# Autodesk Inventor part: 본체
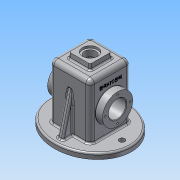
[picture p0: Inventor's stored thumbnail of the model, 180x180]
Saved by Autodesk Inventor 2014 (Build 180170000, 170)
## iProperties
Created: 2017-07
Part Number: 본체
Material: 알루미늄 6061
Document SubType Name: Modeling
Designer: 학생용
Density: 2.71 g/cm^3
Appearance: 알루미늄 - 평지
Mass: 894.559 g
Surface Area: 979.096 cm^2
Volume: 330.096 cm^3
Author: 학생용
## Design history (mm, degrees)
sketch "스케치2"
  geometry: L1 (-75, -65)-(75, -65); L2 (75, -65)-(75, 65); L3 (75, 65)-(-75, 65); L4 (-75, 65)-(-75, -65); L5 (-75, -65)-(75, 65); L6 (75, -65)-(-75, 65); 4 further points; 1 other entity
  constraints: 12 end point, 6 midpoint, 2 horizontal, 2 parallel, 1 perpendicular, 4 other
  dimensions: "d1" = 150 distance of L2.end L3.end; "d2" = 130 distance of L1.end L2.end
extrude "돌출1" new body sketch "스케치2" distance "d3" = 10; taper "d4" = 0 deg
sketch "스케치3"
  geometry: L1 (37, 10)-(-37, 10); L2 (-37, 10)-(-37, 110); L3 (-37, 110)-(37, 110); L4 (37, 110)-(37, 10); L5 (75, 10)-(-75, 10) reference; 2 further points
  constraints: 8 end point, 2 parallel, 1 collinear, 1 horizontal, 1 midpoint, 1 perpendicular, 1 vertical alignment
  dimensions: "d5" = 74 distance of L2.end L3.end; "d6" = 110 distance from line of L3 point (0, 0)
extrude "돌출2" join sketch "스케치3" stored distance "d7" = 74; taper "d8" = 0 deg
fillet "모깎기1" dims "d9" = 8
fillet "모깎기2" dims "d10" = 8
feature "쉘1" dims "d11" = 10, "d12" = 5
sketch "스케치4"
  geometry: L1 (-75, 0)-(-75, 10) reference; L2 (-75, 10)-(-37, 10) reference; L3 (-37, 10)-(-37, 102) reference; L4 (-29, 110)-(29, 110) reference; L5 (37, 102)-(37, 10) reference; L6 (37, 10)-(75, 10) reference; L7 (75, 10)-(75, 0) reference; L8 (75, 0)-(32, 0) reference; L9 (32, 0)-(32, 102) reference; L10 (29, 105)-(-29, 105) reference; L11 (-32, 102)-(-32, 0) reference; L12 (-32, 0)-(-75, 0) reference; L13 (32, 82.5)-(25, 75.5); L14 (25, 75.5)-(25, 55); L15 (25, 55)-(32, 55); L16 (32, 82.5)-(32, 55); L17 (-29, 0)-(29, 0) reference; A1 r 8 centre (-29, 102) between (-29, 110) and (-37, 102) reference; A2 r 8 centre (29, 102) between (37, 102) and (29, 110) reference; A3 r 3 centre (29, 102) between (32, 102) and (29, 105) reference; A4 r 3 centre (-29, 102) between (-29, 105) and (-32, 102) reference; 1 further point
  constraints: 8 end point, 2 perpendicular, 2 point on line, 1 collinear
  dimensions: "d13" = 55 distance between parallel lines of L17 L15; "d14" = 55 diameter of L13.start L15; "d15" = 7 distance between parallel lines of L14 L16; "d16" = 135 deg angle of L9 L13
revolve "회전1" sketch "스케치4" stored, may be unused: angle "d17" = 90 deg
node "작업 평면1"
sketch "스케치5"
  geometry: C1 r 27.5 at (0, 55); 1 further point
  constraints: 1 centre point, 1 vertical alignment
  dimensions: "d19" = 55 distance of point (0, 0) C1.centre; "d20" = 55 diameter of C1
extrude "돌출3" join sketch "스케치5" stored distance "d21" = 74; taper "d22" = 0 deg
node "작업 평면2"
sketch "스케치6"
  geometry: L1 (-20, -20)-(20, -20); L2 (20, -20)-(20, 20); L3 (20, 20)-(-20, 20); L4 (-20, 20)-(-20, -20); L5 (-20, -20)-(20, 20); L6 (20, -20)-(-20, 20); 1 further point
  constraints: 12 end point, 2 midpoint, 2 parallel, 1 horizontal, 1 perpendicular
  dimensions: "d24" = 40 distance of L2.end L3.end; "d25" = 40 distance of L1.end L2.end
extrude "돌출4" join sketch "스케치6" stored distance "d26" = 74; taper "d27" = 0 deg
feature "면 기울기1" dims angle "d28" = 5 deg
sketch "스케치7"
  geometry: 2 further points
  constraints: 1 coincident
hole "구멍1" sketch "스케치7" at (0, 0) diameter "d29" = 21; stored, may be unused: countersink angle "d33" = 90 deg, drill point angle "d35" = 118 deg; dims "d30" = 6, "d31" = 28, "d32" = 4, "d34" = 8
sketch "스케치8"
  geometry: L1 (-65, 0)-(-65, 10) reference; L2 (-65, 10)-(-37, 10) reference; L3 (-37, 10)-(-37, 102) reference; L4 (-29, 110)-(-20, 110) reference; L5 (-20, 110)-(-19.125, 120) reference; L6 (-19.125, 120)-(-14, 120) reference; L7 (-14, 120)-(-14, 116) reference; L8 (-14, 116)-(-10.5, 116) reference; L9 (-10.5, 116)-(-10.5, 105) reference; L10 (-10.5, 105)-(-29, 105) reference; L11 (-32, 102)-(-32, 0) reference; L12 (-32, 0)-(-65, 0) reference; L13 (65, 10)-(65, 0) reference; L14 (65, 0)-(32, 0) reference; L15 (32, 0)-(32, 102) reference; L16 (29, 105)-(10.5, 105) reference; L17 (10.5, 105)-(10.5, 116) reference; L18 (10.5, 116)-(14, 116) reference; L19 (14, 116)-(14, 120) reference; L20 (14, 120)-(19.125, 120) reference; L21 (19.125, 120)-(20, 110) reference; L22 (20, 110)-(29, 110) reference; L23 (37, 102)-(37, 10) reference; L24 (37, 10)-(65, 10) reference; L25 (-55, 10)-(-37, 82.194); A1 r 8 centre (-29, 102) between (-29, 110) and (-37, 102) reference; A2 r 3 centre (-29, 102) between (-29, 105) and (-32, 102) reference; A3 r 3 centre (29, 102) between (32, 102) and (29, 105) reference; A4 r 8 centre (29, 102) between (37, 102) and (29, 110) reference; 1 further point
  constraints: 2 end point, 2 point on line
  dimensions: "d36" = 10 distance from line of L1 L25.start; "d37" = 14 deg angle of L25 L1
feature "리브1" sketch "스케치8" dims "d38" = 1, "d39" = 10, "d40" = 0, "d41" = 0, "d42" = 1, "d43" = 1
hole "구멍2" diameter "d46" = 32; stored, may be unused: countersink angle "d50" = 90 deg, drill point angle "d52" = 118 deg; dims "d44" = 10, "d45" = 10, "d47" = 6, "d48" = 28, "d49" = 4, "d51" = 8
sketch "스케치9"
  geometry: 2 further points
  constraints: 1 horizontal alignment
  dimensions: "d53" = 58 distance of point (58, 0) point (0, 0)
hole "구멍3" sketch "스케치9" at (58, 0) diameter "d54" = 10; stored, may be unused: countersink angle "d58" = 90 deg, drill point angle "d60" = 118 deg; dims "d55" = 6, "d56" = 28, "d57" = 4, "d59" = 8
sketch "스케치10"
  geometry: L1 (-110, 9.875)-(-110, 48.125) reference; L2 (-92, -8)-(0, -8) reference; 2 further points
  constraints: 1 other
  dimensions: "d64" = 30 distance from line of L1 point (-80, 29); "d65" = 37 distance from line of L2 point (-80, 29)
feature "엠보싱1" sketch "스케치10" dims "d66" = 0.5, "d67" = 0
fillet "모깎기3" dims "d68" = 0.5
fillet "모깎기4" dims "d69" = 0.5
fillet "모깎기7" dims "d72" = 3
fillet "모깎기8" dims "d73" = 3
fillet "모깎기9" dims "d74" = 3
fillet "모깎기10" dims "d75" = 3
fillet "모깎기11" dims "d76" = 3
chamfer "모따기1" distance "d77" = 1; stored, may be unused: second distance "d78" = 2, angle "d79" = 45 deg
fillet "모깎기12" dims "d80" = 3
sketch "스케치11"
  geometry: C1 r 27.5 at (0, 0) reference; 2 further points
  constraints: 1 horizontal alignment
  dimensions: "d81" = 22.5 distance of C1.centre point (-22.5, 0)
hole "구멍4" sketch "스케치11" at (-22.5, 0) diameter "d82" = 3.242; stored, may be unused: countersink angle "d86" = 90 deg, drill point angle "d88" = 118 deg; dims "d83" = 8, "d84" = 4, "d85" = 2, "d87" = 10
node "솔리드1"
mirror "대칭1"
mirror "대칭2"
pattern_linear "직사각형 패턴1" dims "d63" = 116
pattern_circular "원형 패턴1" dims angle "d90" = 360 deg
mirror "대칭3"
node "절단 모서리 투영1"
node "절단 모서리 투영2"
